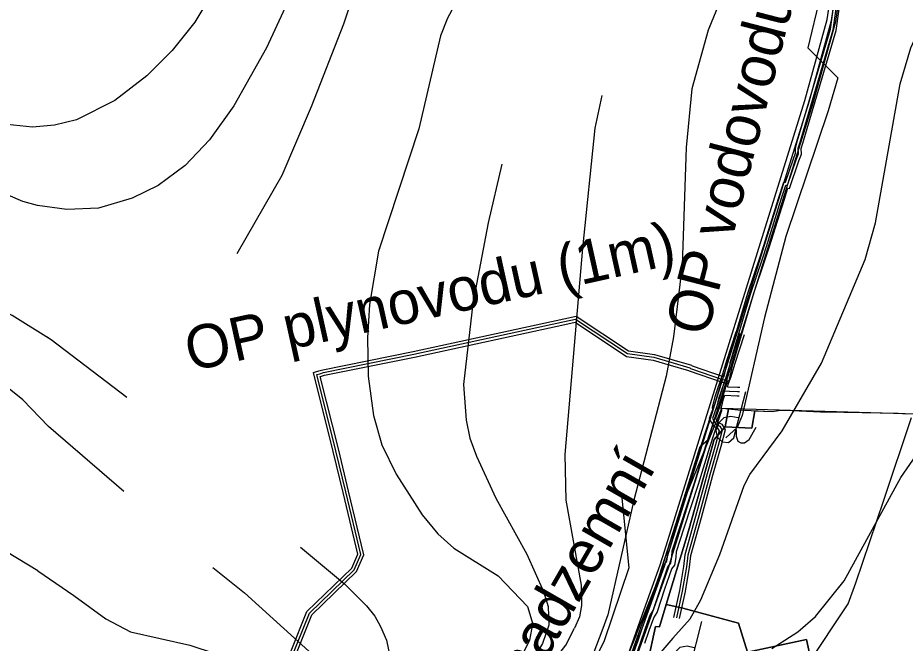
# Model space of a CAD drawing. Extents: x -1900516 to -575031, y -3809306 to -1157387.
# Drawn here: x -578473.4 to -578166.4, y -1158965 to -1158748.8 of the extents above; entities that cross this region are included whole.
import ezdxf

# ---------------------------------------------------------------- set-up
doc = ezdxf.new("R2010")
doc.units = 0
for name, color, linetype in [('01_OBVOD PÚ', 7, 'Continuous'), ('01_VRSTEVNICE', 7, 'Continuous'), ('01_ZASTAV_PLOCHY', 7, 'Continuous'), ('02_KULTURY STAV', 7, 'Continuous'), ('06_ÚSES_BC', 7, 'Continuous'), ('07_ELEKTRO', 7, 'Continuous'), ('07_OCH_P A POPISY TI', 7, 'Continuous'), ('07_PLYNOVOD', 7, 'Continuous'), ('07_SDĚLOVACÍ', 7, 'Continuous'), ('07_VODOVOD', 7, 'Continuous')]:
    doc.layers.add(name, color=color, linetype=linetype)

msp = doc.modelspace()

# ---------------------------------------------------------------- linework, layer by layer
at = {"layer": '01_OBVOD PÚ'}
msp.add_lwpolyline([(-578262.59, -1158974.55), (-578258.79, -1158964.08), (-578255.58, -1158954.53), (-578254.79, -1158952.06), (-578252.25, -1158944.16), (-578250.54, -1158938.84), (-578248.64, -1158933.03), (-578247.39, -1158929.09), (-578244.09, -1158918.49), (-578237.41, -1158897.06), (-578234.58, -1158894.61), (-578232.2, -1158887.06), (-578231.39, -1158884.58), (-578231.15, -1158883.66), (-578228.64, -1158883.92), (-578224.39, -1158884.35), (-578219.76, -1158884.59), (-578212.47, -1158884.96), (-578209.44, -1158884.49), (-578205.56, -1158884.57), (-578195.72, -1158885.02), (-578193.95, -1158885.1), (-578168.85, -1158885.51), (-578165.89, -1158885.7)], dxfattribs=at)
at = {"layer": '01_VRSTEVNICE'}
for points in [[(-578356.22, -1158623.42), (-578365.96, -1158649.24), (-578379.36, -1158678.59), (-578390.37, -1158707.93), (-578401.65, -1158732.77), (-578412.09, -1158750.4), (-578420, -1158760.14), (-578428.74, -1158768.88), (-578439.75, -1158777.49), (-578453.01, -1158784.12), (-578460.63, -1158785.96), (-578468.25, -1158786.66), (-578479.26, -1158785.53)], [(-578340.42, -1158642.89), (-578377.95, -1158738.97), (-578387.4, -1158759.29), (-578398.69, -1158779.33), (-578407.02, -1158791.04), (-578415.48, -1158799.93), (-578424.79, -1158806.84), (-578433.82, -1158811.21), (-578445.39, -1158814.6), (-578456.4, -1158815.16), (-578466.56, -1158813.75), (-578471.64, -1158812.34), (-578493.65, -1158802.89)], [(-578310.65, -1158671.67), (-578318.83, -1158674.49), (-578321.94, -1158670.12), (-578323.21, -1158670.12), (-578327.16, -1158674.64), (-578338.02, -1158691.57), (-578342.4, -1158700.03), (-578347.76, -1158712.73), (-578360.74, -1158751.11), (-578371.88, -1158779.61), (-578382.04, -1158803.31), (-578397.6, -1158830.43)], [(-578201.02, -1158684.65), (-578205.11, -1158696.65), (-578222.33, -1158725.99), (-578229.1, -1158739.54), (-578234.6, -1158753.08), (-578240.24, -1158773.4), (-578242.22, -1158793.72), (-578243.63, -1158834.35), (-578246.59, -1158859.18), (-578249.13, -1158872.73), (-578260.28, -1158915.62), (-578269.33, -1158955.21), (-578271.41, -1158960.82)], [(-578173.86, -1158708.68), (-578177.03, -1158723.45), (-578185.64, -1158724.16), (-578195.85, -1158741.35), (-578200.17, -1158759.29), (-578189.73, -1158769.59), (-578193.12, -1158781.02), (-578207.79, -1158824.48), (-578215.13, -1158852.41), (-578222.89, -1158886.27), (-578224.58, -1158890.51), (-578228.53, -1158894.03)], [(-578319.54, -1158739.26), (-578324.76, -1158748.99), (-578327.16, -1158755.06), (-578334.64, -1158787.23), (-578348.6, -1158829.55), (-578351.71, -1158847.9), (-578352.41, -1158859.47), (-578352.13, -1158872.73), (-578350.3, -1158886.27), (-578347.47, -1158896.43), (-578342.54, -1158906.59), (-578333.51, -1158920.7), (-578328.14, -1158927.19), (-578322.5, -1158932.13), (-578307.26, -1158941.72), (-578297.1, -1158952.3), (-578295.25, -1158958.48)], [(-578246.82, -1158963.27), (-578240.86, -1158956.63), (-578237.19, -1158949.98), (-578230.54, -1158934.4), (-578222.18, -1158910.54), (-578220.21, -1158906.73), (-578209.06, -1158891.64), (-578195.38, -1158868.21), (-578180.28, -1158832.38), (-578176.75, -1158819.68), (-578168.15, -1158771.71), (-578164.48, -1158759.29), (-578159.26, -1158747.58)], [(-578246.82, -1158963.27), (-578240.86, -1158956.63), (-578237.19, -1158949.98), (-578230.54, -1158934.4), (-578222.18, -1158910.54), (-578220.21, -1158906.73), (-578209.06, -1158891.64), (-578195.38, -1158868.21), (-578180.28, -1158832.38), (-578176.75, -1158819.68), (-578168.15, -1158771.71), (-578164.48, -1158759.29), (-578159.26, -1158747.58)], [(-578233.11, -1158749.41), (-578234.6, -1158753.08), (-578240.24, -1158773.4), (-578242.22, -1158793.72), (-578243.63, -1158834.35), (-578246.59, -1158859.18), (-578249.13, -1158872.73), (-578260.28, -1158915.62), (-578269.33, -1158955.21), (-578271.41, -1158960.82)], [(-578233.11, -1158749.41), (-578234.6, -1158753.08), (-578240.24, -1158773.4), (-578242.22, -1158793.72), (-578243.63, -1158834.35), (-578246.59, -1158859.18), (-578249.13, -1158872.73), (-578260.28, -1158915.62), (-578269.33, -1158955.21), (-578271.41, -1158960.82)], [(-578271.41, -1158775.74), (-578273.82, -1158786.95), (-578278.06, -1158828.43), (-578284.12, -1158899.82), (-578283.84, -1158915.62), (-578278.48, -1158944.97), (-578278.41, -1158952), (-578279.12, -1158955.96), (-578280.77, -1158959.87)], [(-578271.41, -1158775.74), (-578273.82, -1158786.95), (-578278.06, -1158828.43), (-578284.12, -1158899.82), (-578283.84, -1158915.62), (-578278.48, -1158944.97), (-578278.41, -1158952), (-578279.12, -1158955.96), (-578280.77, -1158959.87)], [(-578305.96, -1158799.49), (-578310.65, -1158819.68), (-578316.01, -1158847.61), (-578319.26, -1158875.55), (-578318.27, -1158887.97), (-578317, -1158894.18), (-578314.74, -1158900.38), (-578308.09, -1158914.87), (-578297.34, -1158934.26), (-578291.54, -1158947.14), (-578289.98, -1158952.38), (-578289.7, -1158958.8)], [(-578305.96, -1158799.49), (-578310.65, -1158819.68), (-578316.01, -1158847.61), (-578319.26, -1158875.55), (-578318.27, -1158887.97), (-578317, -1158894.18), (-578314.74, -1158900.38), (-578308.09, -1158914.87), (-578297.34, -1158934.26), (-578291.54, -1158947.14), (-578289.98, -1158952.38), (-578289.7, -1158958.8)], [(-578348.28, -1158828.59), (-578348.6, -1158829.55), (-578351.71, -1158847.9), (-578352.41, -1158859.47), (-578352.13, -1158872.73), (-578350.3, -1158886.27), (-578347.47, -1158896.43), (-578342.54, -1158906.59), (-578333.51, -1158920.7), (-578328.14, -1158927.19), (-578322.5, -1158932.13), (-578307.26, -1158941.72), (-578297.1, -1158952.3), (-578295.25, -1158958.48)], [(-578348.28, -1158828.59), (-578348.6, -1158829.55), (-578351.71, -1158847.9), (-578352.41, -1158859.47), (-578352.13, -1158872.73), (-578350.3, -1158886.27), (-578347.47, -1158896.43), (-578342.54, -1158906.59), (-578333.51, -1158920.7), (-578328.14, -1158927.19), (-578322.5, -1158932.13), (-578307.26, -1158941.72), (-578297.1, -1158952.3), (-578295.25, -1158958.48)], [(-578435.66, -1158880.07), (-578461.76, -1158860.17), (-578475.3, -1158851.71), (-578492.23, -1158843.24), (-578502.39, -1158840.14), (-578507.47, -1158839.57), (-578517.63, -1158841.41), (-578526.66, -1158845.5), (-578545.85, -1158857.49), (-578556.29, -1158865.11), (-578578.3, -1158879.08), (-578593.54, -1158886.13), (-578602.01, -1158889.24), (-578617.24, -1158891.92), (-578634.17, -1158891.49), (-578642.64, -1158890.22), (-578659.57, -1158886.27), (-578669.59, -1158882.6)], [(-578435.66, -1158880.07), (-578461.76, -1158860.17), (-578463.38, -1158859.16)], [(-578436.64, -1158912.59), (-578462.75, -1158890.08), (-578471.61, -1158880.87), (-578484.05, -1158871.03), (-578490.54, -1158867.08), (-578499.85, -1158863.7), (-578508.32, -1158862.57), (-578516.36, -1158863.42), (-578529.77, -1158870.33), (-578546.42, -1158882.6), (-578564.47, -1158894.18), (-578580.56, -1158902.22), (-578592.13, -1158906.31), (-578610.75, -1158909.27), (-578629.94, -1158909.7), (-578643.49, -1158908.71), (-578665.36, -1158904.9)], [(-578436.64, -1158912.59), (-578462.75, -1158890.08), (-578471.61, -1158880.87), (-578484.05, -1158871.03), (-578490.54, -1158867.08), (-578499.85, -1158863.7), (-578508.32, -1158862.57), (-578516.36, -1158863.42), (-578529.77, -1158870.33), (-578546.42, -1158882.6), (-578564.47, -1158894.18), (-578580.56, -1158902.22), (-578592.13, -1158906.31), (-578610.75, -1158909.27), (-578629.94, -1158909.7), (-578643.49, -1158908.71), (-578665.36, -1158904.9)], [(-578212.64, -1158966.88), (-578203.59, -1158961.13), (-578197.49, -1158955.83), (-578187.62, -1158943.42), (-578168, -1158907.72), (-578146.7, -1158876.96)], [(-578212.64, -1158966.88), (-578203.59, -1158961.13), (-578197.49, -1158955.83), (-578187.62, -1158943.42), (-578168, -1158907.72), (-578146.7, -1158876.96)], [(-578466.43, -1158940.03), (-578477.28, -1158933.4), (-578504.93, -1158916.61), (-578518.76, -1158910.54), (-578527.51, -1158909.55), (-578537.67, -1158911.81), (-578550.65, -1158919.15), (-578558.96, -1158925.03), (-578563.62, -1158927.44), (-578568.99, -1158929.17)], [(-578466.43, -1158940.03), (-578477.28, -1158933.4), (-578504.93, -1158916.61), (-578518.76, -1158910.54), (-578527.51, -1158909.55), (-578537.67, -1158911.81), (-578550.65, -1158919.15), (-578558.96, -1158925.03), (-578563.62, -1158927.44), (-578568.99, -1158929.17)], [(-578375.55, -1158931.85), (-578360.32, -1158944.46), (-578352.72, -1158952.15)], [(-578375.55, -1158931.85), (-578360.32, -1158944.46), (-578352.72, -1158952.15)], [(-578405.89, -1158938.9), (-578394.93, -1158947.6)], [(-578405.89, -1158938.9), (-578394.93, -1158947.6)], [(-578466.43, -1158940.03), (-578453.93, -1158948.53), (-578442.88, -1158956.64), (-578434.35, -1158961.11), (-578413.8, -1158965.73), (-578411.14, -1158966.57), (-578386.81, -1158974.4), (-578379.82, -1158977.05), (-578371.43, -1158981.53), (-578353.12, -1158994.39), (-578345.71, -1158997.89), (-578338.72, -1158999.57), (-578331.72, -1159000.27), (-578323.61, -1158999.57), (-578316.62, -1158997.47), (-578310.33, -1158994.25), (-578297.89, -1158983.63), (-578293.55, -1158978.31), (-578283.85, -1158965.72), (-578280.77, -1158959.87)], [(-578259.5, -1158962.1), (-578251.25, -1158941.44)], [(-578289.7, -1158958.8), (-578291.93, -1158965.08), (-578297.19, -1158973.84), (-578302.22, -1158980.55), (-578307.95, -1158985.16), (-578317.18, -1158990.2), (-578320.26, -1158991.04), (-578326.41, -1158991.46), (-578335.64, -1158989.92), (-578341.79, -1158987.82), (-578351.02, -1158983.21), (-578358.01, -1158978.87), (-578371.43, -1158968.95), (-578394.93, -1158947.6)], [(-578352.72, -1158952.15), (-578349.9, -1158955.66), (-578347.94, -1158959.3), (-578345.82, -1158963.96), (-578344.03, -1158972.86), (-578341.51, -1158977.75), (-578338.88, -1158979.81), (-578334.94, -1158981.67), (-578325.01, -1158983.07), (-578317.18, -1158982.23), (-578311.59, -1158980.83), (-578306.14, -1158978.31), (-578301.24, -1158973.7), (-578296.32, -1158964.02), (-578295.25, -1158958.48)], [(-578271.41, -1158960.82), (-578276.92, -1158975.38)], [(-578259.5, -1158962.1), (-578265.31, -1158976.36), (-578271.6, -1158994.25), (-578276.36, -1159002.22), (-578280.55, -1159007.54)], [(-578246.82, -1158963.27), (-578254.4, -1158972.16)]]:
    msp.add_lwpolyline(points, dxfattribs=at)
at = {"layer": '01_ZASTAV_PLOCHY'}
msp.add_lwpolyline([(-578229.9, -1158883.79), (-578162.61, -1158885.75), (-578071.15, -1158843.69), (-578016.99, -1158941.28), (-578098.02, -1158993.78), (-578091.23, -1159026.36), (-578080.8, -1159064.08), (-578149.29, -1159109.27), (-578172.64, -1159076.66), (-578183.11, -1159059.57), (-578196.12, -1159046.14), (-578205.02, -1159044.49), (-578253.95, -1159059.24), (-578257.82, -1159045.7), (-578274.88, -1159048.83), (-578315.72, -1159049.17), (-578328.26, -1159051.22), (-578290.62, -1159018.54), (-578282.01, -1159008.64), (-578266.85, -1158984.77), (-578251.4, -1158941.5), (-578244.09, -1158918.49)], close=True, dxfattribs=at)
at = {"layer": '02_KULTURY STAV'}
for points in [[(-578224.24, -1158887.16), (-578226.74, -1158886.68), (-578229.24, -1158887.08), (-578230.85, -1158888.69), (-578231.91, -1158891.52), (-578231.5, -1158893.86), (-578229.81, -1158895.47), (-578227.55, -1158895.63), (-578225.69, -1158894.02), (-578221.58, -1158878.05)], [(-578262.59, -1158974.55), (-578258.79, -1158964.08), (-578255.58, -1158954.53), (-578254.79, -1158952.06), (-578252.25, -1158944.16), (-578250.54, -1158938.84), (-578248.64, -1158933.03), (-578247.39, -1158929.09), (-578244.09, -1158918.49), (-578237.41, -1158897.06), (-578234.58, -1158894.61), (-578232.2, -1158887.06), (-578231.39, -1158884.58), (-578231.15, -1158883.66), (-578228.64, -1158883.92), (-578227.6, -1158884.03), (-578228.72, -1158890.21), (-578232.52, -1158894.58), (-578241.14, -1158925.32), (-578242.27, -1158929.33), (-578249.09, -1158951.69), (-578251.42, -1158959.33), (-578252.76, -1158959.27), (-578255.51, -1158971.51)], [(-578199.07, -1158970.68), (-578200.59, -1158963.71), (-578220.97, -1158968.17), (-578224.09, -1158958.09), (-578243.42, -1158952.96), (-578249.09, -1158951.69), (-578242.27, -1158929.33), (-578241.14, -1158925.32), (-578232.52, -1158894.58), (-578228.72, -1158890.21), (-578219.45, -1158890.74), (-578218.49, -1158884.65), (-578212.47, -1158884.96), (-578209.44, -1158884.49), (-578205.56, -1158884.57), (-578195.72, -1158885.02), (-578193.95, -1158885.1), (-578168.85, -1158885.51), (-578165.89, -1158885.7)], [(-578199.07, -1158970.68), (-578200.59, -1158963.71), (-578220.97, -1158968.17), (-578224.09, -1158958.09), (-578243.42, -1158952.96), (-578249.09, -1158951.69), (-578242.27, -1158929.33), (-578241.14, -1158925.32), (-578232.52, -1158894.58), (-578228.72, -1158890.21), (-578219.45, -1158890.74), (-578218.49, -1158884.65), (-578212.47, -1158884.96), (-578209.44, -1158884.49), (-578205.56, -1158884.57), (-578195.72, -1158885.02), (-578193.95, -1158885.1), (-578168.85, -1158885.51), (-578165.89, -1158885.7)], [(-578224.88, -1158891.28), (-578224.88, -1158893.45), (-578224.32, -1158895.15), (-578223.35, -1158895.79), (-578222.06, -1158895.71), (-578220.37, -1158894.58), (-578217.95, -1158890.39)], [(-578239.42, -1158966.58), (-578241.92, -1158966.1), (-578244.42, -1158966.5), (-578246.04, -1158968.11), (-578247.08, -1158970.94), (-578246.68, -1158973.28), (-578244.98, -1158974.89), (-578242.73, -1158975.05), (-578240.87, -1158973.44), (-578236.76, -1158957.47)]]:
    msp.add_lwpolyline(points, dxfattribs=at)
for points in [[(-578228.72, -1158890.21), (-578227.6, -1158884.03), (-578224.39, -1158884.35), (-578219.76, -1158884.59), (-578218.49, -1158884.65), (-578219.45, -1158890.74)], [(-578255.51, -1158971.51), (-578252.76, -1158959.27), (-578251.42, -1158959.33), (-578249.09, -1158951.69), (-578243.42, -1158952.96), (-578224.09, -1158958.09), (-578220.97, -1158968.17), (-578200.59, -1158963.71), (-578199.07, -1158970.68), (-578253.49, -1158982.58), (-578255.01, -1158975.61), (-578248.17, -1158974.12), (-578248, -1158973.38)]]:
    msp.add_lwpolyline(points, close=True, dxfattribs=at)
at = {"layer": '06_ÚSES_BC'}
msp.add_lwpolyline([(-578200.33, -1158972.77), (-578186.24, -1158951.4), (-578183.56, -1158944.13), (-578173.9, -1158915.59), (-578164.26, -1158887.05)], dxfattribs=at)
at = {"layer": '07_ELEKTRO'}
msp.add_lwpolyline([(-578264.6, -1158913.72), (-578262, -1158939), (-578270.57, -1158964.18), (-578284.77, -1158993.44), (-578309.47, -1159021.37)], dxfattribs=at)
msp.add_lwpolyline([(-578264.6, -1158913.72), (-578262, -1158939), (-578270.57, -1158964.18), (-578284.77, -1158993.44), (-578309.47, -1159021.37)], dxfattribs=at)
at = {"layer": '07_OCH_P A POPISY TI'}
for p, q in [((-578233.51, -1158886.11), (-578232.94, -1158884.38)), ((-578230.66, -1158887.04), (-578229.84, -1158884.54))]:
    msp.add_line(p, q, dxfattribs=at)
for points in [[(-578249.69, -1158933.16), (-578201.17, -1158777.44), (-578193.43, -1158749.48), (-578188.4, -1158715.87), (-578181.06, -1158709.09)], [(-578246.82, -1158934.05), (-578198.29, -1158778.28), (-578190.49, -1158750.1), (-578185.59, -1158717.35), (-578179.02, -1158711.29)], [(-578384.24, -1158981.22), (-578373.36, -1158954.09), (-578357.86, -1158939.08), (-578355.74, -1158934.28), (-578360.88, -1158912.91), (-578364.3, -1158898.73), (-578371.14, -1158871.5), (-578369.21, -1158870.91), (-578367.84, -1158870.49), (-578336.63, -1158864.14), (-578284.55, -1158852.87), (-578280.23, -1158851.93), (-578262.15, -1158863.97), (-578253.21, -1158865.23), (-578247.21, -1158866.97), (-578240.39, -1158868.94), (-578240.17, -1158869.14), (-578229.42, -1158872.82), (-578229.23, -1158872.82), (-578229.08, -1158872.86), (-578228.02, -1158868.26), (-578227.93, -1158867.86), (-578220.93, -1158844.06), (-578220.89, -1158843.98), (-578216.62, -1158831.47), (-578215.4, -1158827.6), (-578210.27, -1158811.3), (-578208.49, -1158805.62), (-578207.89, -1158805.68), (-578205.09, -1158797.61), (-578204.36, -1158795.7), (-578204.44, -1158793.82), (-578203.78, -1158791.6), (-578192.31, -1158752.79), (-578189.73, -1158734.12)], [(-578382.5, -1158982.26), (-578371.66, -1158955.23), (-578356.18, -1158940.24), (-578353.64, -1158934.46), (-578358.94, -1158912.45), (-578362.36, -1158898.25), (-578368.74, -1158872.86), (-578368.63, -1158872.83), (-578367.34, -1158872.43), (-578336.21, -1158866.1), (-578284.13, -1158854.83), (-578280.63, -1158854.07), (-578262.87, -1158865.89), (-578253.63, -1158867.19), (-578247.77, -1158868.89), (-578241.41, -1158870.72), (-578241.23, -1158870.9), (-578229.76, -1158874.82), (-578229.49, -1158874.82), (-578229.07, -1158874.93), (-578227.6, -1158875.3), (-578226.08, -1158868.72), (-578225.99, -1158868.38), (-578219.07, -1158844.8), (-578219.05, -1158844.76), (-578214.72, -1158832.09), (-578213.5, -1158828.2), (-578208.37, -1158811.9), (-578207.07, -1158807.78), (-578206.53, -1158807.84), (-578203.21, -1158798.29), (-578202.34, -1158796.02), (-578202.42, -1158794.06), (-578201.86, -1158792.16), (-578190.35, -1158753.21), (-578187.73, -1158734.26)], [(-578231.38, -1158877.3), (-578230.39, -1158874.3), (-578229.56, -1158871.96), (-578228.17, -1158867.28), (-578224.94, -1158857.36)], [(-578227.91, -1158876.36), (-578227.55, -1158875.28), (-578226.7, -1158872.88), (-578225.31, -1158868.18), (-578222.08, -1158858.28)], [(-578229.78, -1158873.67), (-578232.45, -1158882.47), (-578234.22, -1158887.41), (-578233.53, -1158888.63), (-578232.79, -1158889.94), (-578231.32, -1158890.75), (-578230.82, -1158891.59), (-578232.1, -1158896.46), (-578234.98, -1158906.51), (-578238.93, -1158921.19), (-578242.64, -1158934.42), (-578243.11, -1158938.5), (-578244.54, -1158946.82), (-578246.56, -1158956.08)], [(-578227.86, -1158874.25), (-578230.55, -1158883.09), (-578232.02, -1158887.23), (-578231.79, -1158887.65), (-578231.33, -1158888.46), (-578229.88, -1158889.27), (-578228.68, -1158891.29), (-578230.18, -1158896.98), (-578233.06, -1158907.05), (-578237.01, -1158921.73), (-578240.68, -1158934.8), (-578241.13, -1158938.78), (-578242.58, -1158947.2), (-578244.6, -1158956.51)], [(-578232.94, -1158884.38), (-578233.12, -1158883.57), (-578232.19, -1158879.74), (-578231.38, -1158877.3)], [(-578227.91, -1158876.36), (-578224.4, -1158876.51), (-578223.6, -1158876.57)], [(-578229.84, -1158884.54), (-578230.04, -1158883.61), (-578229.31, -1158880.56), (-578228.89, -1158879.32)], [(-578228.89, -1158879.32), (-578224.58, -1158879.51), (-578223.83, -1158879.56)], [(-578259.36, -1158964.05), (-578257.83, -1158959.64), (-578256.14, -1158954.85), (-578254.95, -1158953.08), (-578252.41, -1158945.32), (-578249.84, -1158937.9), (-578248.92, -1158936.72), (-578248.63, -1158935.12), (-578248.56, -1158932.79), (-578245.7, -1158924.25), (-578240.81, -1158909.16), (-578236.87, -1158896.39), (-578233.51, -1158886.11)], [(-578256.52, -1158965.03), (-578254.99, -1158960.62), (-578253.44, -1158956.21), (-578252.23, -1158954.4), (-578249.57, -1158946.28), (-578247.18, -1158939.36), (-578246.1, -1158938), (-578245.63, -1158935.44), (-578245.58, -1158933.31), (-578242.86, -1158925.19), (-578237.95, -1158910.06), (-578234.01, -1158897.29), (-578230.66, -1158887.04)], [(-578304.03, -1159027.81), (-578286.6, -1159011.47), (-578270.51, -1158990.17), (-578264.96, -1158976.49), (-578256.68, -1158953.35), (-578251.19, -1158937.97), (-578249.69, -1158933.16)], [(-578301.98, -1159030), (-578284.36, -1159013.48), (-578267.88, -1158991.67), (-578262.15, -1158977.55), (-578253.86, -1158954.36), (-578248.34, -1158938.92), (-578246.82, -1158934.05)], [(-578261.06, -1158968.94), (-578259.36, -1158964.05)]]:
    msp.add_lwpolyline(points, dxfattribs=at)
at = {"layer": '07_PLYNOVOD'}
for points in [[(-578383.37, -1158981.74), (-578372.51, -1158954.66), (-578357.02, -1158939.66), (-578354.69, -1158934.37), (-578359.91, -1158912.68), (-578363.33, -1158898.49), (-578369.94, -1158872.18), (-578368.92, -1158871.87), (-578367.59, -1158871.46), (-578336.42, -1158865.12), (-578284.34, -1158853.85), (-578280.43, -1158853), (-578262.51, -1158864.93), (-578253.42, -1158866.21), (-578247.49, -1158867.93), (-578240.9, -1158869.83), (-578240.7, -1158870.02), (-578229.59, -1158873.82), (-578229.36, -1158873.82), (-578228.82, -1158873.96), (-578228.34, -1158874.08), (-578227.05, -1158868.49), (-578226.96, -1158868.12), (-578220, -1158844.43), (-578219.97, -1158844.37), (-578215.67, -1158831.78), (-578214.45, -1158827.9), (-578209.32, -1158811.6), (-578207.78, -1158806.7), (-578207.21, -1158806.76), (-578204.15, -1158797.95), (-578203.35, -1158795.86), (-578203.43, -1158793.94), (-578202.82, -1158791.88), (-578191.33, -1158753), (-578188.73, -1158734.19)], [(-578228.82, -1158873.96), (-578231.5, -1158882.78), (-578233.12, -1158887.32), (-578232.66, -1158888.14), (-578232.06, -1158889.2), (-578230.6, -1158890.01), (-578229.75, -1158891.44), (-578231.14, -1158896.72), (-578234.02, -1158906.78), (-578237.97, -1158921.46), (-578241.66, -1158934.61), (-578242.12, -1158938.64), (-578243.56, -1158947.01), (-578245.58, -1158956.3)]]:
    msp.add_lwpolyline(points, dxfattribs=at)
at = {"layer": '07_SDĚLOVACÍ'}
for points in [[(-578229.96, -1158877.77), (-578228.97, -1158874.79), (-578228.13, -1158872.42), (-578226.74, -1158867.73), (-578223.51, -1158857.82)], [(-578231.39, -1158884.46), (-578231.58, -1158883.59), (-578230.75, -1158880.15), (-578229.96, -1158877.77)], [(-578229.96, -1158877.77), (-578224.49, -1158878.01), (-578223.71, -1158878.07)], [(-578231.39, -1158884.46), (-578230.81, -1158884.25)], [(-578257.94, -1158964.54), (-578256.41, -1158960.13), (-578254.79, -1158955.53), (-578253.59, -1158953.74), (-578250.99, -1158945.8), (-578248.51, -1158938.63), (-578247.51, -1158937.36), (-578247.13, -1158935.28), (-578247.07, -1158933.05), (-578244.28, -1158924.72), (-578239.38, -1158909.61), (-578235.44, -1158896.84), (-578232.08, -1158886.58)], [(-578232.08, -1158886.58), (-578231.39, -1158884.46)], [(-578259.65, -1158969.45), (-578257.94, -1158964.54)]]:
    msp.add_lwpolyline(points, dxfattribs=at)
at = {"layer": '07_VODOVOD'}
for points in [[(-578248.26, -1158933.61), (-578199.73, -1158777.86), (-578191.96, -1158749.79), (-578186.99, -1158716.61), (-578180.04, -1158710.19)], [(-578303.01, -1159028.9), (-578285.48, -1159012.48), (-578269.19, -1158990.92), (-578263.56, -1158977.02), (-578255.27, -1158953.85), (-578249.76, -1158938.45), (-578248.26, -1158933.61)]]:
    msp.add_lwpolyline(points, dxfattribs=at)

# ---------------------------------------------------------------- texts
at = {"layer": '07_OCH_P A POPISY TI'}
for s, rotation, p in [('OP vodovodu (1,5 m)', 75.4416, (-578235.1, -1158859.47)), ('OP plynovodu (1m)', 12.5009, (-578413.64, -1158871.16)), ('NN nadzemní', 60.134, (-578313.43, -1159010.49))]:
    msp.add_text(s, height=15, rotation=rotation, dxfattribs=at).set_placement(p)

doc.saveas('drawing.dxf')
